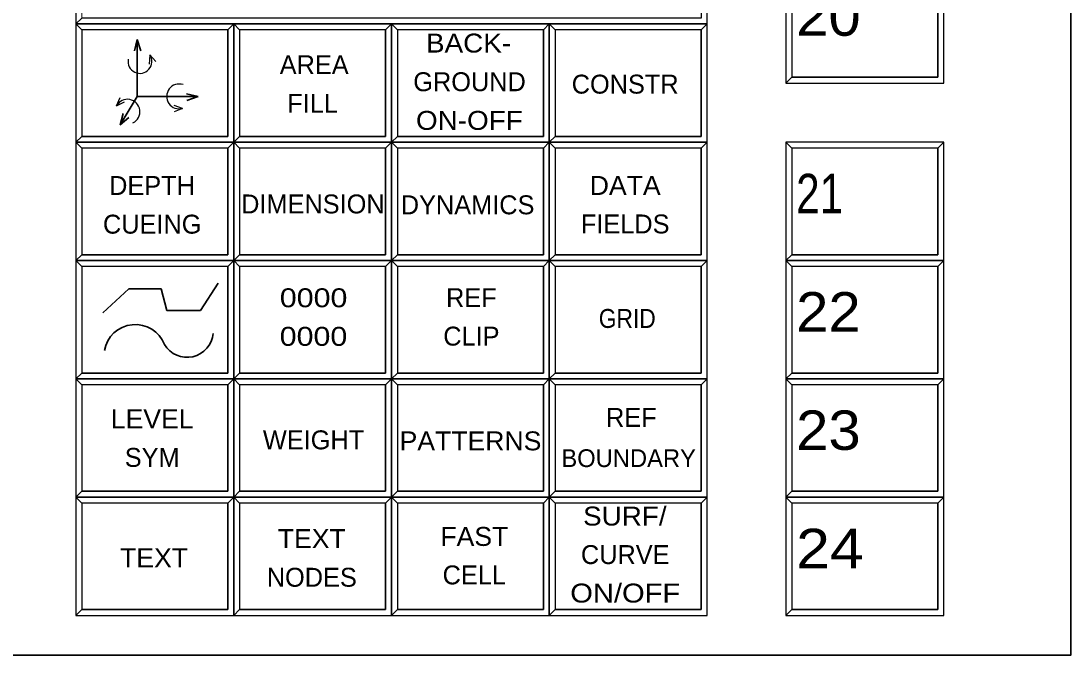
# Model space of a CAD drawing. Extents: x 95906.9 to 95918.9, y 90964.8 to 90972.9.
# Drawn here: x 95916.193 to 95918.855, y 90964.762 to 90966.369 of the extents above; entities that cross this region are included whole.
import ezdxf
from ezdxf.enums import TextEntityAlignment as Align

# ---------------------------------------------------------------- set-up
doc = ezdxf.new("R2010")
doc.units = 0
doc.header["$LTSCALE"] = 0.019
for name, color, linetype, lineweight in [('1', 7, 'Continuous', 25), ('11', 7, 'Continuous', 25), ('12', 7, 'Continuous', 25), ('2', 7, 'Continuous', 13), ('3', 7, 'Continuous', 25), ('4', 7, 'Continuous', 35), ('6', 7, 'Continuous', 35), ('7', 7, 'Continuous', 35)]:
    doc.layers.add(name, color=color, linetype=linetype, lineweight=lineweight)

msp = doc.modelspace()

# ---------------------------------------------------------------- linework, layer by layer
at = {"layer": '1'}
for points in [[(95918.1323, 90966.2117), (95918.5323, 90966.2117), (95918.5323, 90966.5117), (95918.1323, 90966.5117)], [(95916.3323, 90966.3617), (95917.9323, 90966.3617), (95917.9323, 90966.4617), (95916.3323, 90966.4617)], [(95916.3323, 90966.0617), (95916.7323, 90966.0617), (95916.7323, 90966.3617), (95916.3323, 90966.3617)], [(95916.7323, 90966.0617), (95917.1323, 90966.0617), (95917.1323, 90966.3617), (95916.7323, 90966.3617)], [(95917.1323, 90966.0617), (95917.5323, 90966.0617), (95917.5323, 90966.3617), (95917.1323, 90966.3617)], [(95917.5323, 90966.0617), (95917.9323, 90966.0617), (95917.9323, 90966.3617), (95917.5323, 90966.3617)], [(95916.3323, 90965.7617), (95916.7323, 90965.7617), (95916.7323, 90966.0617), (95916.3323, 90966.0617)], [(95916.7323, 90965.7617), (95917.1323, 90965.7617), (95917.1323, 90966.0617), (95916.7323, 90966.0617)], [(95917.1323, 90965.7617), (95917.5323, 90965.7617), (95917.5323, 90966.0617), (95917.1323, 90966.0617)], [(95917.5323, 90965.7617), (95917.9323, 90965.7617), (95917.9323, 90966.0617), (95917.5323, 90966.0617)], [(95918.1323, 90965.7617), (95918.5323, 90965.7617), (95918.5323, 90966.0617), (95918.1323, 90966.0617)], [(95916.3323, 90965.4617), (95916.7323, 90965.4617), (95916.7323, 90965.7617), (95916.3323, 90965.7617)], [(95916.7323, 90965.4617), (95917.1323, 90965.4617), (95917.1323, 90965.7617), (95916.7323, 90965.7617)], [(95917.1323, 90965.4617), (95917.5323, 90965.4617), (95917.5323, 90965.7617), (95917.1323, 90965.7617)], [(95917.5323, 90965.4617), (95917.9323, 90965.4617), (95917.9323, 90965.7617), (95917.5323, 90965.7617)], [(95918.1323, 90965.4617), (95918.5323, 90965.4617), (95918.5323, 90965.7617), (95918.1323, 90965.7617)], [(95916.3323, 90965.1617), (95916.7323, 90965.1617), (95916.7323, 90965.4617), (95916.3323, 90965.4617)], [(95916.7323, 90965.1617), (95917.1323, 90965.1617), (95917.1323, 90965.4617), (95916.7323, 90965.4617)], [(95917.1323, 90965.1617), (95917.5323, 90965.1617), (95917.5323, 90965.4617), (95917.1323, 90965.4617)], [(95917.5323, 90965.1617), (95917.9323, 90965.1617), (95917.9323, 90965.4617), (95917.5323, 90965.4617)], [(95918.1323, 90965.1617), (95918.5323, 90965.1617), (95918.5323, 90965.4617), (95918.1323, 90965.4617)], [(95916.3323, 90964.8617), (95916.7323, 90964.8617), (95916.7323, 90965.1617), (95916.3323, 90965.1617)], [(95916.7323, 90964.8617), (95917.1323, 90964.8617), (95917.1323, 90965.1617), (95916.7323, 90965.1617)], [(95917.1323, 90964.8617), (95917.5323, 90964.8617), (95917.5323, 90965.1617), (95917.1323, 90965.1617)], [(95917.5323, 90964.8617), (95917.9323, 90964.8617), (95917.9323, 90965.1617), (95917.5323, 90965.1617)], [(95918.1323, 90964.8617), (95918.5323, 90964.8617), (95918.5323, 90965.1617), (95918.1323, 90965.1617)]]:
    msp.add_lwpolyline(points, close=True, dxfattribs=at)
at = {"layer": '11'}
for points in [[(95918.1473, 90966.2267), (95918.5173, 90966.2267), (95918.5173, 90966.4967), (95918.1473, 90966.4967)], [(95916.3473, 90966.0767), (95916.7173, 90966.0767), (95916.7173, 90966.3467), (95916.3473, 90966.3467)], [(95916.7473, 90966.0767), (95917.1173, 90966.0767), (95917.1173, 90966.3467), (95916.7473, 90966.3467)], [(95917.1473, 90966.0767), (95917.5173, 90966.0767), (95917.5173, 90966.3467), (95917.1473, 90966.3467)], [(95917.5473, 90966.0767), (95917.9173, 90966.0767), (95917.9173, 90966.3467), (95917.5473, 90966.3467)], [(95916.3473, 90965.7767), (95916.7173, 90965.7767), (95916.7173, 90966.0467), (95916.3473, 90966.0467)], [(95916.7473, 90965.7767), (95917.1173, 90965.7767), (95917.1173, 90966.0467), (95916.7473, 90966.0467)], [(95917.1473, 90965.7767), (95917.5173, 90965.7767), (95917.5173, 90966.0467), (95917.1473, 90966.0467)], [(95917.5473, 90965.7767), (95917.9173, 90965.7767), (95917.9173, 90966.0467), (95917.5473, 90966.0467)], [(95918.1473, 90965.7767), (95918.5173, 90965.7767), (95918.5173, 90966.0467), (95918.1473, 90966.0467)], [(95916.3473, 90965.4767), (95916.7173, 90965.4767), (95916.7173, 90965.7467), (95916.3473, 90965.7467)], [(95916.7473, 90965.4767), (95917.1173, 90965.4767), (95917.1173, 90965.7467), (95916.7473, 90965.7467)], [(95917.1473, 90965.4767), (95917.5173, 90965.4767), (95917.5173, 90965.7467), (95917.1473, 90965.7467)], [(95917.5473, 90965.4767), (95917.9173, 90965.4767), (95917.9173, 90965.7467), (95917.5473, 90965.7467)], [(95918.1473, 90965.4767), (95918.5173, 90965.4767), (95918.5173, 90965.7467), (95918.1473, 90965.7467)], [(95916.3473, 90965.1767), (95916.7173, 90965.1767), (95916.7173, 90965.4467), (95916.3473, 90965.4467)], [(95916.7473, 90965.1767), (95917.1173, 90965.1767), (95917.1173, 90965.4467), (95916.7473, 90965.4467)], [(95917.1473, 90965.1767), (95917.5173, 90965.1767), (95917.5173, 90965.4467), (95917.1473, 90965.4467)], [(95917.5473, 90965.1767), (95917.9173, 90965.1767), (95917.9173, 90965.4467), (95917.5473, 90965.4467)], [(95918.1473, 90965.1767), (95918.5173, 90965.1767), (95918.5173, 90965.4467), (95918.1473, 90965.4467)], [(95916.3473, 90964.8767), (95916.7173, 90964.8767), (95916.7173, 90965.1467), (95916.3473, 90965.1467)], [(95916.7473, 90964.8767), (95917.1173, 90964.8767), (95917.1173, 90965.1467), (95916.7473, 90965.1467)], [(95917.1473, 90964.8767), (95917.5173, 90964.8767), (95917.5173, 90965.1467), (95917.1473, 90965.1467)], [(95917.5473, 90964.8767), (95917.9173, 90964.8767), (95917.9173, 90965.1467), (95917.5473, 90965.1467)], [(95918.1473, 90964.8767), (95918.5173, 90964.8767), (95918.5173, 90965.1467), (95918.1473, 90965.1467)]]:
    msp.add_lwpolyline(points, close=True, dxfattribs=at)
at = {"layer": '12'}
msp.add_lwpolyline([(95917.5473, 90965.4767), (95917.9173, 90965.4767), (95917.9173, 90965.7467), (95917.5473, 90965.7467)], close=True, dxfattribs=at)
at = {"layer": '2'}
for points in [[(95918.1323, 90966.5117), (95918.1323, 90966.2117), (95918.1473, 90966.2267), (95918.1473, 90966.4967), (95918.5173, 90966.4967), (95918.5323, 90966.5117)], [(95916.3323, 90966.4617), (95916.3323, 90966.3617), (95916.3473, 90966.3767), (95916.3473, 90966.4467), (95917.9173, 90966.4467), (95917.9323, 90966.4617)], [(95916.3323, 90966.3617), (95916.3323, 90966.0617), (95916.3473, 90966.0767), (95916.3473, 90966.3467), (95916.7173, 90966.3467), (95916.7323, 90966.3617)], [(95916.7323, 90966.3617), (95916.7323, 90966.0617), (95916.7473, 90966.0767), (95916.7473, 90966.3467), (95917.1173, 90966.3467), (95917.1323, 90966.3617)], [(95917.1323, 90966.3617), (95917.1323, 90966.0617), (95917.1473, 90966.0767), (95917.1473, 90966.3467), (95917.5173, 90966.3467), (95917.5323, 90966.3617)], [(95917.5323, 90966.3617), (95917.5323, 90966.0617), (95917.5473, 90966.0767), (95917.5473, 90966.3467), (95917.9173, 90966.3467), (95917.9323, 90966.3617)], [(95916.3323, 90966.0617), (95916.3323, 90965.7617), (95916.3473, 90965.7767), (95916.3473, 90966.0467), (95916.7173, 90966.0467), (95916.7323, 90966.0617)], [(95916.7323, 90966.0617), (95916.7323, 90965.7617), (95916.7473, 90965.7767), (95916.7473, 90966.0467), (95917.1173, 90966.0467), (95917.1323, 90966.0617)], [(95917.1323, 90966.0617), (95917.1323, 90965.7617), (95917.1473, 90965.7767), (95917.1473, 90966.0467), (95917.5173, 90966.0467), (95917.5323, 90966.0617)], [(95917.5323, 90966.0617), (95917.5323, 90965.7617), (95917.5473, 90965.7767), (95917.5473, 90966.0467), (95917.9173, 90966.0467), (95917.9323, 90966.0617)], [(95918.1323, 90966.0617), (95918.1323, 90965.7617), (95918.1473, 90965.7767), (95918.1473, 90966.0467), (95918.5173, 90966.0467), (95918.5323, 90966.0617)], [(95916.3323, 90965.7617), (95916.3323, 90965.4617), (95916.3473, 90965.4767), (95916.3473, 90965.7467), (95916.7173, 90965.7467), (95916.7323, 90965.7617)], [(95916.7323, 90965.7617), (95916.7323, 90965.4617), (95916.7473, 90965.4767), (95916.7473, 90965.7467), (95917.1173, 90965.7467), (95917.1323, 90965.7617)], [(95917.1323, 90965.7617), (95917.1323, 90965.4617), (95917.1473, 90965.4767), (95917.1473, 90965.7467), (95917.5173, 90965.7467), (95917.5323, 90965.7617)], [(95917.5323, 90965.7617), (95917.5323, 90965.4617), (95917.5473, 90965.4767), (95917.5473, 90965.7467), (95917.9173, 90965.7467), (95917.9323, 90965.7617)], [(95918.1323, 90965.7617), (95918.1323, 90965.4617), (95918.1473, 90965.4767), (95918.1473, 90965.7467), (95918.5173, 90965.7467), (95918.5323, 90965.7617)], [(95916.3323, 90965.4617), (95916.3323, 90965.1617), (95916.3473, 90965.1767), (95916.3473, 90965.4467), (95916.7173, 90965.4467), (95916.7323, 90965.4617)], [(95916.7323, 90965.4617), (95916.7323, 90965.1617), (95916.7473, 90965.1767), (95916.7473, 90965.4467), (95917.1173, 90965.4467), (95917.1323, 90965.4617)], [(95917.1323, 90965.4617), (95917.1323, 90965.1617), (95917.1473, 90965.1767), (95917.1473, 90965.4467), (95917.5173, 90965.4467), (95917.5323, 90965.4617)], [(95917.5323, 90965.4617), (95917.5323, 90965.1617), (95917.5473, 90965.1767), (95917.5473, 90965.4467), (95917.9173, 90965.4467), (95917.9323, 90965.4617)], [(95918.1323, 90965.4617), (95918.1323, 90965.1617), (95918.1473, 90965.1767), (95918.1473, 90965.4467), (95918.5173, 90965.4467), (95918.5323, 90965.4617)], [(95916.3323, 90965.1617), (95916.3323, 90964.8617), (95916.3473, 90964.8767), (95916.3473, 90965.1467), (95916.7173, 90965.1467), (95916.7323, 90965.1617)], [(95916.7323, 90965.1617), (95916.7323, 90964.8617), (95916.7473, 90964.8767), (95916.7473, 90965.1467), (95917.1173, 90965.1467), (95917.1323, 90965.1617)], [(95917.1323, 90965.1617), (95917.1323, 90964.8617), (95917.1473, 90964.8767), (95917.1473, 90965.1467), (95917.5173, 90965.1467), (95917.5323, 90965.1617)], [(95917.5323, 90965.1617), (95917.5323, 90964.8617), (95917.5473, 90964.8767), (95917.5473, 90965.1467), (95917.9173, 90965.1467), (95917.9323, 90965.1617)], [(95918.1323, 90965.1617), (95918.1323, 90964.8617), (95918.1473, 90964.8767), (95918.1473, 90965.1467), (95918.5173, 90965.1467), (95918.5323, 90965.1617)]]:
    msp.add_lwpolyline(points, close=True, dxfattribs=at)
at = {"layer": '3'}
for points in [[(95918.1323, 90966.2117), (95918.5323, 90966.2117), (95918.5323, 90966.5117), (95918.5173, 90966.4967), (95918.5173, 90966.2267), (95918.1473, 90966.2267)], [(95916.3323, 90966.3617), (95917.9323, 90966.3617), (95917.9323, 90966.4617), (95917.9173, 90966.4467), (95917.9173, 90966.3767), (95916.3473, 90966.3767)], [(95916.3323, 90966.0617), (95916.7323, 90966.0617), (95916.7323, 90966.3617), (95916.7173, 90966.3467), (95916.7173, 90966.0767), (95916.3473, 90966.0767)], [(95916.7323, 90966.0617), (95917.1323, 90966.0617), (95917.1323, 90966.3617), (95917.1173, 90966.3467), (95917.1173, 90966.0767), (95916.7473, 90966.0767)], [(95917.1323, 90966.0617), (95917.5323, 90966.0617), (95917.5323, 90966.3617), (95917.5173, 90966.3467), (95917.5173, 90966.0767), (95917.1473, 90966.0767)], [(95917.5323, 90966.0617), (95917.9323, 90966.0617), (95917.9323, 90966.3617), (95917.9173, 90966.3467), (95917.9173, 90966.0767), (95917.5473, 90966.0767)], [(95916.3323, 90965.7617), (95916.7323, 90965.7617), (95916.7323, 90966.0617), (95916.7173, 90966.0467), (95916.7173, 90965.7767), (95916.3473, 90965.7767)], [(95916.7323, 90965.7617), (95917.1323, 90965.7617), (95917.1323, 90966.0617), (95917.1173, 90966.0467), (95917.1173, 90965.7767), (95916.7473, 90965.7767)], [(95917.1323, 90965.7617), (95917.5323, 90965.7617), (95917.5323, 90966.0617), (95917.5173, 90966.0467), (95917.5173, 90965.7767), (95917.1473, 90965.7767)], [(95917.5323, 90965.7617), (95917.9323, 90965.7617), (95917.9323, 90966.0617), (95917.9173, 90966.0467), (95917.9173, 90965.7767), (95917.5473, 90965.7767)], [(95918.1323, 90965.7617), (95918.5323, 90965.7617), (95918.5323, 90966.0617), (95918.5173, 90966.0467), (95918.5173, 90965.7767), (95918.1473, 90965.7767)], [(95916.3323, 90965.4617), (95916.7323, 90965.4617), (95916.7323, 90965.7617), (95916.7173, 90965.7467), (95916.7173, 90965.4767), (95916.3473, 90965.4767)], [(95916.7323, 90965.4617), (95917.1323, 90965.4617), (95917.1323, 90965.7617), (95917.1173, 90965.7467), (95917.1173, 90965.4767), (95916.7473, 90965.4767)], [(95917.1323, 90965.4617), (95917.5323, 90965.4617), (95917.5323, 90965.7617), (95917.5173, 90965.7467), (95917.5173, 90965.4767), (95917.1473, 90965.4767)], [(95917.5323, 90965.4617), (95917.9323, 90965.4617), (95917.9323, 90965.7617), (95917.9173, 90965.7467), (95917.9173, 90965.4767), (95917.5473, 90965.4767)], [(95918.1323, 90965.4617), (95918.5323, 90965.4617), (95918.5323, 90965.7617), (95918.5173, 90965.7467), (95918.5173, 90965.4767), (95918.1473, 90965.4767)], [(95916.3323, 90965.1617), (95916.7323, 90965.1617), (95916.7323, 90965.4617), (95916.7173, 90965.4467), (95916.7173, 90965.1767), (95916.3473, 90965.1767)], [(95916.7323, 90965.1617), (95917.1323, 90965.1617), (95917.1323, 90965.4617), (95917.1173, 90965.4467), (95917.1173, 90965.1767), (95916.7473, 90965.1767)], [(95917.1323, 90965.1617), (95917.5323, 90965.1617), (95917.5323, 90965.4617), (95917.5173, 90965.4467), (95917.5173, 90965.1767), (95917.1473, 90965.1767)], [(95917.5323, 90965.1617), (95917.9323, 90965.1617), (95917.9323, 90965.4617), (95917.9173, 90965.4467), (95917.9173, 90965.1767), (95917.5473, 90965.1767)], [(95918.1323, 90965.1617), (95918.5323, 90965.1617), (95918.5323, 90965.4617), (95918.5173, 90965.4467), (95918.5173, 90965.1767), (95918.1473, 90965.1767)], [(95916.3323, 90964.8617), (95916.7323, 90964.8617), (95916.7323, 90965.1617), (95916.7173, 90965.1467), (95916.7173, 90964.8767), (95916.3473, 90964.8767)], [(95916.7323, 90964.8617), (95917.1323, 90964.8617), (95917.1323, 90965.1617), (95917.1173, 90965.1467), (95917.1173, 90964.8767), (95916.7473, 90964.8767)], [(95917.1323, 90964.8617), (95917.5323, 90964.8617), (95917.5323, 90965.1617), (95917.5173, 90965.1467), (95917.5173, 90964.8767), (95917.1473, 90964.8767)], [(95917.5323, 90964.8617), (95917.9323, 90964.8617), (95917.9323, 90965.1617), (95917.9173, 90965.1467), (95917.9173, 90964.8767), (95917.5473, 90964.8767)], [(95918.1323, 90964.8617), (95918.5323, 90964.8617), (95918.5323, 90965.1617), (95918.5173, 90965.1467), (95918.5173, 90964.8767), (95918.1473, 90964.8767)]]:
    msp.add_lwpolyline(points, close=True, dxfattribs=at)
at = {"layer": '4'}
for p, q in [((95916.3473, 90966.3467), (95916.3323, 90966.3617)), ((95916.7473, 90966.3467), (95916.7323, 90966.3617)), ((95917.1473, 90966.3467), (95917.1323, 90966.3617)), ((95917.5473, 90966.3467), (95917.5323, 90966.3617)), ((95916.3473, 90966.0467), (95916.3323, 90966.0617)), ((95916.7473, 90966.0467), (95916.7323, 90966.0617)), ((95917.1473, 90966.0467), (95917.1323, 90966.0617)), ((95917.5473, 90966.0467), (95917.5323, 90966.0617)), ((95918.1473, 90966.0467), (95918.1323, 90966.0617)), ((95916.3473, 90965.7467), (95916.3323, 90965.7617)), ((95916.7473, 90965.7467), (95916.7323, 90965.7617)), ((95917.1473, 90965.7467), (95917.1323, 90965.7617)), ((95917.5473, 90965.7467), (95917.5323, 90965.7617)), ((95918.1473, 90965.7467), (95918.1323, 90965.7617)), ((95916.3473, 90965.4467), (95916.3323, 90965.4617)), ((95916.7473, 90965.4467), (95916.7323, 90965.4617)), ((95917.1473, 90965.4467), (95917.1323, 90965.4617)), ((95917.5473, 90965.4467), (95917.5323, 90965.4617)), ((95918.1473, 90965.4467), (95918.1323, 90965.4617)), ((95916.3473, 90965.1467), (95916.3323, 90965.1617)), ((95916.7473, 90965.1467), (95916.7323, 90965.1617)), ((95917.1473, 90965.1467), (95917.1323, 90965.1617)), ((95917.5473, 90965.1467), (95917.5323, 90965.1617)), ((95918.1473, 90965.1467), (95918.1323, 90965.1617))]:
    msp.add_line(p, q, dxfattribs=at)
at = {"layer": '6'}
for p, q in [((95916.4878, 90966.3224), (95916.4806, 90966.2937)), ((95916.4878, 90966.3224), (95916.4964, 90966.2937)), ((95916.6425, 90966.1777), (95916.6124, 90966.1849)), ((95916.6425, 90966.1777), (95916.6138, 90966.1677)), ((95916.4448, 90966.1061), (95916.452, 90966.1348))]:
    msp.add_line(p, q, dxfattribs=at)
at = {"layer": '6', "lineweight": 25}
for p, q in [((95916.5193, 90966.2837), (95916.5179, 90966.2594)), ((95916.5193, 90966.2837), (95916.535, 90966.2665)), ((95916.4354, 90966.1544), (95916.4446, 90966.1756)), ((95916.4354, 90966.1544), (95916.4557, 90966.1645)), ((95916.6024, 90966.1476), (95916.5809, 90966.1548)), ((95916.6024, 90966.1476), (95916.5809, 90966.1391))]:
    msp.add_line(p, q, dxfattribs=at)
at = {"layer": '6'}
for points in [[(95916.4878, 90966.3224), (95916.4878, 90966.1777), (95916.6425, 90966.1777)], [(95916.4878, 90966.1777), (95916.4448, 90966.1061), (95916.4663, 90966.1247)], [(95916.4001, 90965.6293), (95916.4665, 90965.6897), (95916.548, 90965.6897), (95916.5631, 90965.6354), (95916.6477, 90965.6354), (95916.6929, 90965.7048)]]:
    msp.add_lwpolyline(points, dxfattribs=at)
at = {"layer": '6', "lineweight": 25}
for centre, radius, start, end in [((95916.4945, 90966.2665), 0.0302, 168.919, 34.7521), ((95916.5938, 90966.1779), 0.0315, 71.4799, 285.8557), ((95916.4629, 90966.1391), 0.0315, 296.4799, 150.8557)]:
    msp.add_arc(centre, radius, start, end, dxfattribs=at)
at = {"layer": '6'}
for centre, radius, start, end in [((95916.4829, 90965.5203), 0.0793, 21.2607, 170.3098), ((95916.6139, 90965.5828), 0.0664, 210.6372, 355.2163)]:
    msp.add_arc(centre, radius, start, end, dxfattribs=at)
at = {"layer": '7'}
msp.add_lwpolyline([(95906.8548, 90972.8617), (95918.8548, 90972.8617), (95918.8548, 90964.7617), (95906.8548, 90964.7617)], close=True, dxfattribs=at)

# ---------------------------------------------------------------- texts
at = {"layer": '6'}
for s, width, p in [('20', 1.1, (95918.1581, 90966.3318)), ('21', 0.8, (95918.1581, 90965.8818)), ('22', 1.1, (95918.1581, 90965.5818)), ('23', 1.1, (95918.1581, 90965.2818)), ('24', 1.15, (95918.1581, 90964.9818))]:
    msp.add_text(s, height=0.1, dxfattribs=dict(at, width=width)).set_placement(p)
for s, height, width, p in [('BACK-', 0.048, 1.1, (95917.3276, 90966.2892)), ('ON-OFF', 0.048, 1.1, (95917.3296, 90966.0932)), ('DATA', 0.048, 1.05, (95917.7247, 90965.9282)), ('0000', 0.048, 1.2, (95916.9348, 90965.6434)), ('GRID', 0.048, 0.9, (95917.7299, 90965.591)), ('0000', 0.048, 1.2, (95916.9345, 90965.5456)), ('LEVEL', 0.048, 1.05, (95916.5256, 90965.3365)), ('PATTERNS', 0.048, 1.05, (95917.3325, 90965.2806)), ('SURF/', 0.04799, 1.1, (95917.7238, 90965.0899)), ('TEXT', 0.048, 1.05, (95916.9302, 90965.0328)), ('FAST', 0.048, 1.05, (95917.3422, 90965.0383)), ('TEXT', 0.048, 1.05, (95916.5303, 90964.984)), ('ON/OFF', 0.04799, 1.15, (95917.7248, 90964.8947))]:
    msp.add_text(s, height=height, dxfattribs=dict(at, width=width)).set_placement(p, align=Align.CENTER)
for s, height, p in [('AREA', 0.048, (95916.9363, 90966.2344)), ('GROUND', 0.048, (95917.3301, 90966.1912)), ('CONSTR', 0.048, (95917.7246, 90966.1851)), ('FILL', 0.048, (95916.9324, 90966.1364)), ('DEPTH', 0.048, (95916.5252, 90965.9281)), ('DIMENSION', 0.048, (95916.933, 90965.8813)), ('DYNAMICS', 0.048, (95917.3252, 90965.8791)), ('CUEING', 0.048, (95916.5256, 90965.8301)), ('FIELDS', 0.048, (95917.7247, 90965.8306)), ('REF', 0.04799, (95917.3348, 90965.6438)), ('CLIP', 0.04799, (95917.3348, 90965.5462)), ('REF', 0.048, (95917.7403, 90965.3402)), ('WEIGHT', 0.048, (95916.9346, 90965.2832)), ('SYM', 0.048, (95916.5256, 90965.2387)), ('BOUNDARY', 0.045, (95917.7334, 90965.2383)), ('CURVE', 0.04799, (95917.7248, 90964.9923)), ('NODES', 0.048, (95916.9302, 90964.9348)), ('CELL', 0.048, (95917.3421, 90964.9407))]:
    msp.add_text(s, height=height, dxfattribs=at).set_placement(p, align=Align.CENTER)

doc.saveas('drawing.dxf')
